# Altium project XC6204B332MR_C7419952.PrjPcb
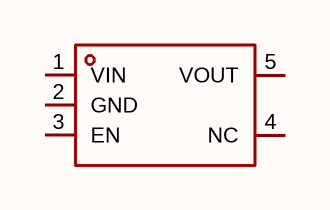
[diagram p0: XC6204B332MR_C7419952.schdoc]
1 sheet, 1 parts. Net scope: global (net labels, ports and power ports of the same name join across sheets).

## Sheet XC6204B332MR_C7419952.schdoc
size 127 x 101 mm

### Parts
U?  xc6204b332mr_c7419952  [SOT-23-5_L2.9-W1.6-P0.95-LS2.8-BR]  (value not drawn)

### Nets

Not connected (* = marked no-connect by the designer): U? 1(VIN) 2(GND) 3(EN) 4(NC) 5(VOUT)

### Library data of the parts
U? = xc6204b332mr_c7419952: 输出极性:正极;工作电压:24V;输出电压:3.3V;输出电流:300mA;电源纹波抑制比(PSRR):70dB@(1kHz);输出类型:固定;; Manufacturer: TECH PUBLIC(台舟); AddInBom: yes; ModelId: 7ba65df16e7b4570af156e925f9c37fe; ModelTransform: 114.173,114.173,0,90,0,0,0,0,0; Output Configuration: 正极; Voltage - Supply: 24V; Output Voltage: 3.3V; Output Current: 300mA; Voltage Dropout: 420mV@(100mA); standby current: 2uA; Output Type: 固定; Number of Outputs: 1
